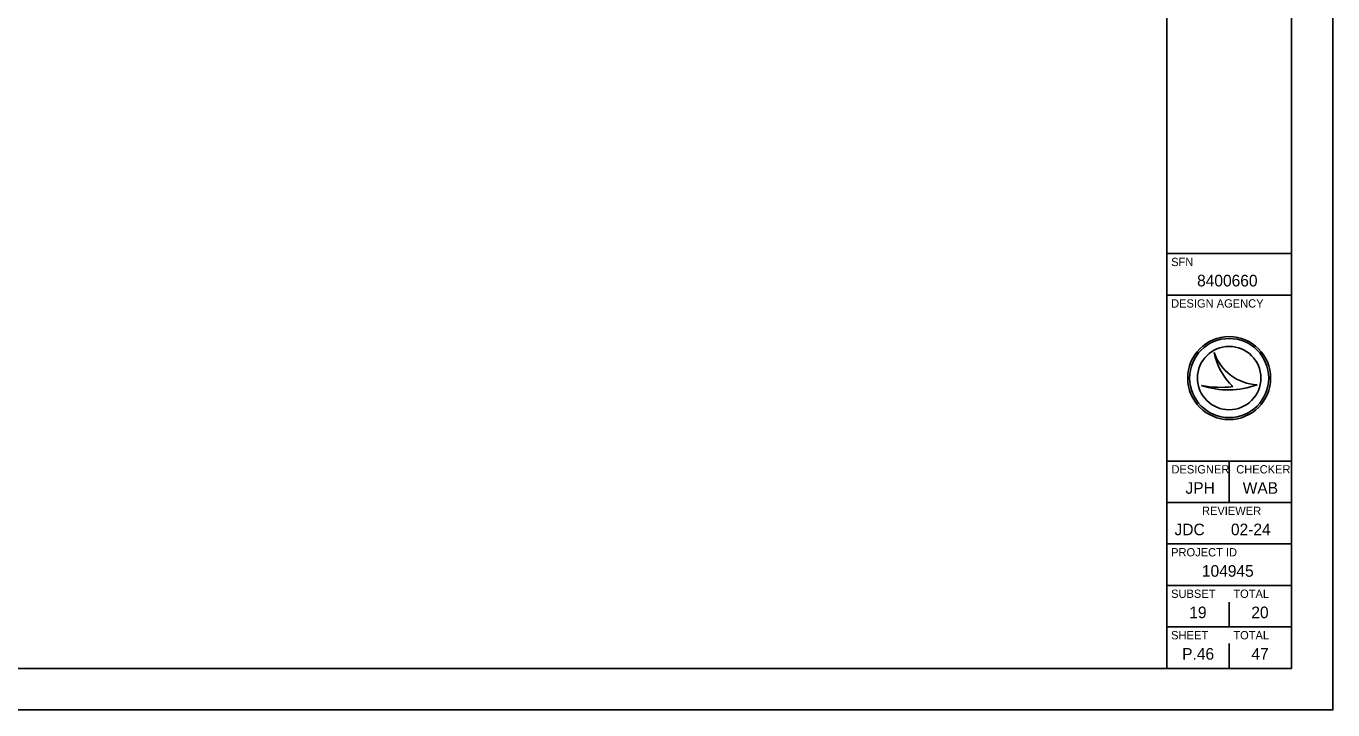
# Model space of a CAD drawing. Extents: x 0 to 340, y 0 to 220.
# Drawn here: x 182.5 to 340, y 0 to 82.4 of the extents above; entities that cross this region are included whole.
import ezdxf

# ---------------------------------------------------------------- set-up
doc = ezdxf.new("R2010")
doc.units = 0
for name, color, linetype in [('SH_Border', 7, 'Continuous'), ('SH_Cut_Line', 7, 'Continuous'), ('SH_Data', 7, 'Continuous')]:
    doc.layers.add(name, color=color, linetype=linetype)

msp = doc.modelspace()

# ---------------------------------------------------------------- linework, layer by layer
at = {"layer": 'SH_Border'}
for p, q in [((320, 5), (320, 215)), ((320, 55), (335, 55)), ((320, 50), (335, 50)), ((320, 30), (335, 30)), ((327.5, 30), (327.5, 25)), ((320, 25), (335, 25)), ((320, 20), (335, 20)), ((320, 15), (335, 15)), ((320, 10), (335, 10))]:
    msp.add_line(p, q, dxfattribs=at)
msp.add_lwpolyline([(15, 215), (335, 215), (335, 5), (15, 5)], close=True, dxfattribs=at)
at = {"layer": 'SH_Cut_Line'}
msp.add_lwpolyline([(0, 0), (340, 0), (340, 220), (0, 220)], close=True, dxfattribs=at)
at = {"layer": 'SH_Data'}
for p, q in [((325.67, 43.1), (325.67, 43.1)), ((327.5, 40), (327.5, 40)), ((324.17, 39.1), (324.17, 39.1)), ((330.87, 39.19), (330.87, 39.19)), ((327.5, 10), (327.5, 13)), ((327.5, 5), (327.5, 8)), ((323.75, 6.75), (323.75, 6.75))]:
    msp.add_line(p, q, dxfattribs=at)
for radius in [5, 4.77, 4.77, 3.82]:
    msp.add_circle((327.5, 40), radius, dxfattribs=at)
for centre, radius, start, end in [((331.16, 44.98), 5.8, 198.9257, 198.9319), ((333.47, 44.7), 7.96, 191.6379, 191.6421), ((331.16, 44.98), 5.8, 198.9319, 267.1657), ((333.47, 44.7), 7.96, 191.6421, 226.0947), ((327.39, 48.7), 10.13, 251.4576, 290.0832), ((326.48, 51.54), 12.66, 259.4964, 259.4995), ((327.39, 48.7), 10.13, 251.4527, 251.4576), ((326.48, 51.54), 12.66, 259.4995, 276.6672)]:
    msp.add_arc(centre, radius, start, end, dxfattribs=at)

# ---------------------------------------------------------------- texts
for s, height, p in [('SFN', 1, (320.5, 53.5)), ('8400660', 1.4, (323.63, 51.05)), ('DESIGN AGENCY', 1, (320.5, 48.5)), ('DESIGNER', 1, (320.54, 28.5)), ('CHECKER', 1, (328.35, 28.5)), ('JPH', 1.4, (322.23, 26.05)), ('WAB', 1.4, (329.13, 26.05)), ('REVIEWER', 1, (324.22, 23.5)), ('JDC', 1.4, (320.91, 21.05)), ('02-24', 1.4, (327.71, 21.05)), ('PROJECT ID', 1, (320.5, 18.5)), ('104945', 1.4, (324.21, 16.05)), ('SUBSET', 1, (320.5, 13.5)), ('TOTAL', 1, (328, 13.5)), ('19', 1.4, (322.69, 11.05)), ('20', 1.4, (330.17, 11.05)), ('SHEET', 1, (320.5, 8.5)), ('TOTAL', 1, (328, 8.5)), ('P.46', 1.4, (321.83, 6.05)), ('47', 1.4, (330.18, 6.05))]:
    msp.add_text(s, height=height, dxfattribs=at).set_placement(p)

doc.saveas('drawing.dxf')
